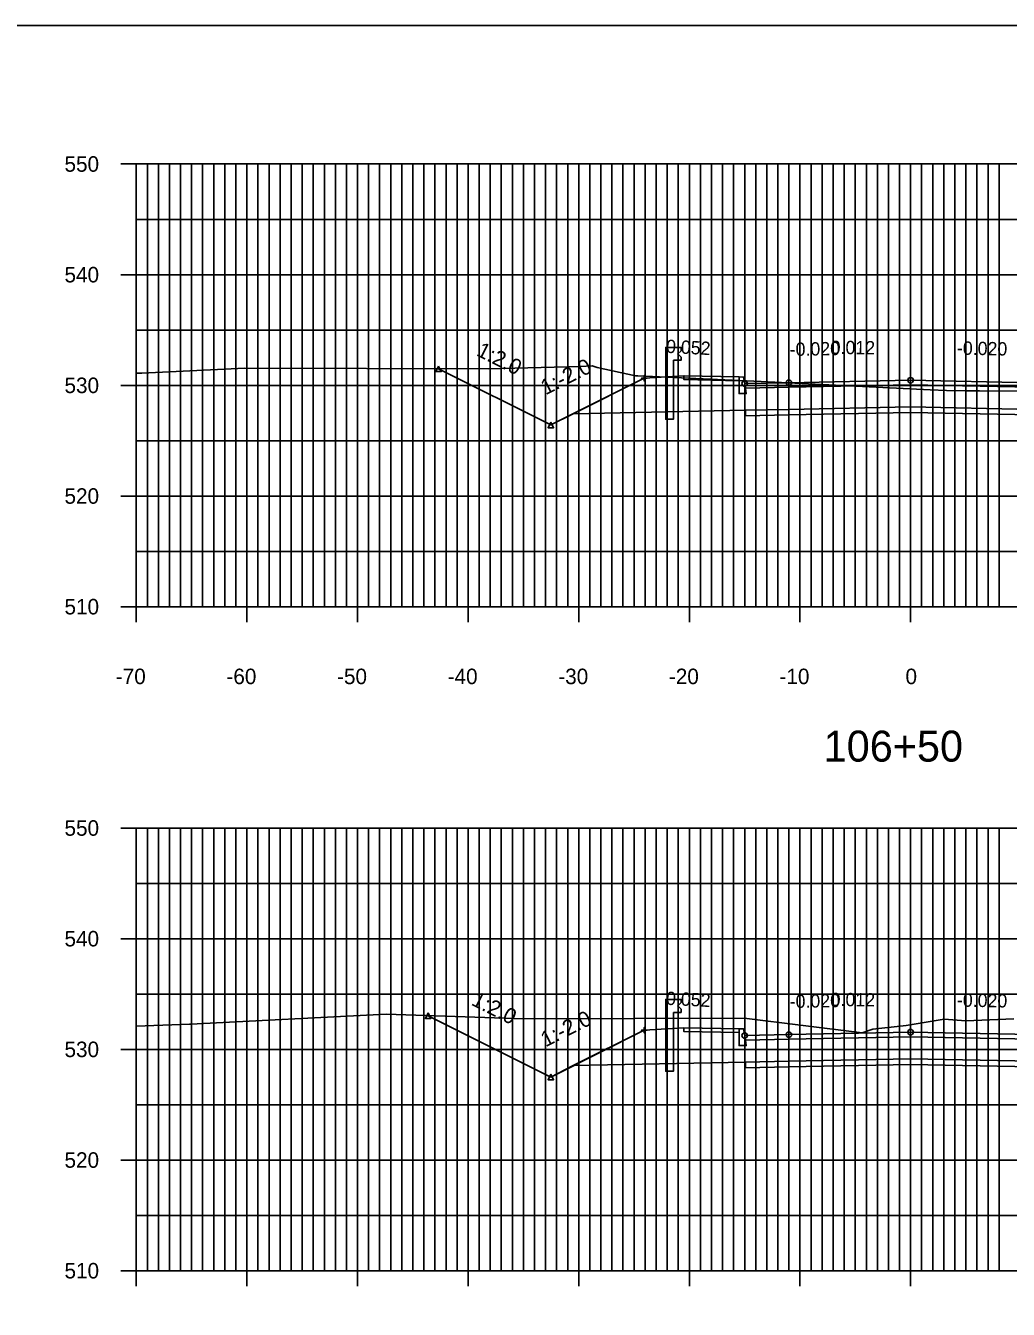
# Model space of a CAD drawing. Extents: x 1509063 to 1512863, y 401160 to 402918.
# Drawn here: x 1511982.7 to 1512071.6, y 402346.1 to 402462.1 of the extents above; entities that cross this region are included whole.
import ezdxf

# ---------------------------------------------------------------- set-up
doc = ezdxf.new("R2010")
doc.units = 0
for name, color, linetype in [('DD_P', 7, 'Continuous'), ('LCUT_P', 7, 'Continuous'), ('NBL1', 7, 'Continuous'), ('PET_P', 7, 'Continuous'), ('PRC', 7, 'Continuous'), ('PSP_P', 7, 'Continuous'), ('RBS_P', 7, 'Continuous'), ('RCC_P', 7, 'Continuous'), ('RGR_P', 7, 'Continuous'), ('XAX_P', 7, 'Continuous'), ('XAXTIC_P', 7, 'Continuous'), ('XAXTXT_P_T', 7, 'Continuous'), ('XGL_P', 7, 'Continuous'), ('XSL1_P', 7, 'Continuous'), ('XSL1_P_T', 7, 'Continuous'), ('XSL2_P', 7, 'Continuous'), ('XSL3_P', 7, 'Continuous'), ('XSLOG', 7, 'Continuous')]:
    doc.layers.add(name, color=color, linetype=linetype)

msp = doc.modelspace()

# ---------------------------------------------------------------- linework, layer by layer
at = {"layer": 'DD_P'}
for points in [[(1512042.23, 402430.44), (1512038.65, 402430.22), (1512030.2, 402426), (1512020.05, 402431.07)], [(1512042.23, 402371.52), (1512038.65, 402371.31), (1512030.2, 402367.08), (1512019.12, 402372.62)]]:
    msp.add_lwpolyline(points, dxfattribs=at)
for points in [[(1512030.2, 402426.25), (1512030.45, 402425.75), (1512029.95, 402425.75)], [(1512030.2, 402367.33), (1512030.45, 402366.83), (1512029.95, 402366.83)]]:
    msp.add_lwpolyline(points, close=True, dxfattribs=at)
at = {"layer": 'LCUT_P'}
for points in [[(1512020.05, 402431.32), (1512020.3, 402430.82), (1512019.8, 402430.82)], [(1512019.12, 402372.87), (1512019.37, 402372.37), (1512018.87, 402372.37)]]:
    msp.add_lwpolyline(points, close=True, dxfattribs=at)
at = {"layer": 'NBL1'}
msp.add_lwpolyline([(1512142.73, 402252.08), (1511822.73, 402252.08), (1511822.73, 402462.08), (1512142.73, 402462.08)], close=True, dxfattribs=at)
at = {"layer": 'PET_P'}
for centre in [(1512051.73, 402429.82), (1512051.73, 402370.91)]:
    msp.add_circle(centre, 0.25, dxfattribs=at)
at = {"layer": 'PRC'}
for centre in [(1512062.73, 402430.04), (1512062.73, 402371.13)]:
    msp.add_circle(centre, 0.25, dxfattribs=at)
at = {"layer": 'PSP_P'}
for centre in [(1512047.73, 402429.74), (1512047.73, 402370.83)]:
    msp.add_circle(centre, 0.25, dxfattribs=at)
at = {"layer": 'RBS_P'}
for points in [[(1512038.65, 402430.22), (1512038.65, 402430.47), (1512038.65, 402430.22), (1512038.4, 402430.22), (1512038.65, 402430.22), (1512038.65, 402429.97), (1512038.65, 402430.22), (1512038.9, 402430.22)], [(1512038.65, 402371.31), (1512038.65, 402371.56), (1512038.65, 402371.31), (1512038.4, 402371.31), (1512038.65, 402371.31), (1512038.65, 402371.06), (1512038.65, 402371.31), (1512038.9, 402371.31)]]:
    msp.add_lwpolyline(points, dxfattribs=at)
for points in [[(1512047.8, 402429.33), (1512051.73, 402429.41), (1512062.72, 402429.63), (1512062.72, 402427.63), (1512051.73, 402427.41), (1512047.8, 402427.33), (1512032.24, 402427.02), (1512038.65, 402430.22), (1512042.23, 402430.44), (1512042.23, 402430.1), (1512047.23, 402430), (1512047.23, 402428.84), (1512047.88, 402428.84)], [(1512062.72, 402429.63), (1512062.72, 402427.63), (1512073.73, 402427.41), (1512077.73, 402427.33), (1512088.24, 402427.12), (1512077.73, 402429.74), (1512077.73, 402429.33), (1512073.73, 402429.41)], [(1512047.8, 402370.42), (1512051.73, 402370.5), (1512062.72, 402370.72), (1512062.72, 402368.72), (1512051.73, 402368.5), (1512047.8, 402368.42), (1512032.24, 402368.11), (1512038.65, 402371.31), (1512042.23, 402371.52), (1512042.23, 402371.19), (1512047.23, 402371.09), (1512047.23, 402369.92), (1512047.88, 402369.92)], [(1512062.72, 402370.72), (1512062.72, 402368.72), (1512073.73, 402368.5), (1512077.73, 402368.42), (1512088.24, 402368.21), (1512077.73, 402370.83), (1512077.73, 402370.42), (1512073.73, 402370.5)]]:
    msp.add_lwpolyline(points, close=True, dxfattribs=at)
at = {"layer": 'RCC_P'}
for points in [[(1512047.73, 402429.74), (1512047.63, 402430.33), (1512047.23, 402430.34), (1512047.23, 402428.84), (1512047.88, 402428.84)], [(1512047.73, 402370.83), (1512047.63, 402371.42), (1512047.23, 402371.42), (1512047.23, 402369.92), (1512047.88, 402369.92)]]:
    msp.add_lwpolyline(points, close=True, dxfattribs=at)
at = {"layer": 'RGR_P'}
for points in [[(1512041.29, 402431.84), (1512041.98, 402431.84), (1512041.98, 402432.14), (1512041.68, 402432.42), (1512041.98, 402432.71), (1512041.98, 402433.01), (1512040.6, 402433.01), (1512040.6, 402426.51), (1512041.29, 402426.51)], [(1512041.29, 402372.92), (1512041.98, 402372.92), (1512041.98, 402373.22), (1512041.68, 402373.51), (1512041.98, 402373.8), (1512041.98, 402374.1), (1512040.6, 402374.1), (1512040.6, 402367.6), (1512041.29, 402367.6)]]:
    msp.add_lwpolyline(points, close=True, dxfattribs=at)
at = {"layer": 'XAX_P'}
for p, q in [((1511992.73, 402409.58), (1511992.73, 402449.58)), ((1512062.73, 402409.58), (1512062.73, 402449.58)), ((1511992.73, 402409.58), (1512132.73, 402409.58)), ((1511992.73, 402349.58), (1511992.73, 402389.58)), ((1512062.73, 402349.58), (1512062.73, 402389.58)), ((1511992.73, 402349.58), (1512132.73, 402349.58))]:
    msp.add_line(p, q, dxfattribs=at)
at = {"layer": 'XAXTIC_P'}
for p, q in [((1511991.33, 402449.58), (1511994.13, 402449.58)), ((1512061.33, 402449.58), (1512064.13, 402449.58)), ((1511991.33, 402439.58), (1511994.13, 402439.58)), ((1512061.33, 402439.58), (1512064.13, 402439.58)), ((1511991.33, 402429.58), (1511994.13, 402429.58)), ((1512061.33, 402429.58), (1512064.13, 402429.58)), ((1511991.33, 402419.58), (1511994.13, 402419.58)), ((1512061.33, 402419.58), (1512064.13, 402419.58)), ((1511992.73, 402408.18), (1511992.73, 402410.98)), ((1512002.73, 402408.18), (1512002.73, 402410.98)), ((1512012.73, 402408.18), (1512012.73, 402410.98)), ((1512022.73, 402408.18), (1512022.73, 402410.98)), ((1512032.73, 402408.18), (1512032.73, 402410.98)), ((1512042.73, 402408.18), (1512042.73, 402410.98)), ((1512052.73, 402408.18), (1512052.73, 402410.98)), ((1512062.73, 402408.18), (1512062.73, 402410.98)), ((1511991.33, 402409.58), (1511994.13, 402409.58)), ((1512061.33, 402409.58), (1512064.13, 402409.58)), ((1511991.33, 402389.58), (1511994.13, 402389.58)), ((1512061.33, 402389.58), (1512064.13, 402389.58)), ((1511991.33, 402379.58), (1511994.13, 402379.58)), ((1512061.33, 402379.58), (1512064.13, 402379.58)), ((1511991.33, 402369.58), (1511994.13, 402369.58)), ((1512061.33, 402369.58), (1512064.13, 402369.58)), ((1511991.33, 402359.58), (1511994.13, 402359.58)), ((1512061.33, 402359.58), (1512064.13, 402359.58)), ((1511992.73, 402348.18), (1511992.73, 402350.98)), ((1512002.73, 402348.18), (1512002.73, 402350.98)), ((1512012.73, 402348.18), (1512012.73, 402350.98)), ((1512022.73, 402348.18), (1512022.73, 402350.98)), ((1512032.73, 402348.18), (1512032.73, 402350.98)), ((1512042.73, 402348.18), (1512042.73, 402350.98)), ((1512052.73, 402348.18), (1512052.73, 402350.98)), ((1512062.73, 402348.18), (1512062.73, 402350.98)), ((1511991.33, 402349.58), (1511994.13, 402349.58)), ((1512061.33, 402349.58), (1512064.13, 402349.58))]:
    msp.add_line(p, q, dxfattribs=at)
at = {"layer": 'XGL_P'}
for p, q in [((1511992.73, 402449.58), (1512132.73, 402449.58)), ((1511992.73, 402409.58), (1511992.73, 402449.58)), ((1511993.73, 402409.58), (1511993.73, 402449.58)), ((1511994.73, 402409.58), (1511994.73, 402449.58)), ((1511995.73, 402409.58), (1511995.73, 402449.58)), ((1511996.73, 402409.58), (1511996.73, 402449.58)), ((1511997.73, 402409.58), (1511997.73, 402449.58)), ((1511998.73, 402409.58), (1511998.73, 402449.58)), ((1511999.73, 402409.58), (1511999.73, 402449.58)), ((1512000.73, 402409.58), (1512000.73, 402449.58)), ((1512001.73, 402409.58), (1512001.73, 402449.58)), ((1512002.73, 402409.58), (1512002.73, 402449.58)), ((1512003.73, 402409.58), (1512003.73, 402449.58)), ((1512004.73, 402409.58), (1512004.73, 402449.58)), ((1512005.73, 402409.58), (1512005.73, 402449.58)), ((1512006.73, 402409.58), (1512006.73, 402449.58)), ((1512007.73, 402409.58), (1512007.73, 402449.58)), ((1512008.73, 402409.58), (1512008.73, 402449.58)), ((1512009.73, 402409.58), (1512009.73, 402449.58)), ((1512010.73, 402409.58), (1512010.73, 402449.58)), ((1512011.73, 402409.58), (1512011.73, 402449.58)), ((1512012.73, 402409.58), (1512012.73, 402449.58)), ((1512013.73, 402409.58), (1512013.73, 402449.58)), ((1512014.73, 402409.58), (1512014.73, 402449.58)), ((1512015.73, 402409.58), (1512015.73, 402449.58)), ((1512016.73, 402409.58), (1512016.73, 402449.58)), ((1512017.73, 402409.58), (1512017.73, 402449.58)), ((1512018.73, 402409.58), (1512018.73, 402449.58)), ((1512019.73, 402409.58), (1512019.73, 402449.58)), ((1512020.73, 402409.58), (1512020.73, 402449.58)), ((1512021.73, 402409.58), (1512021.73, 402449.58)), ((1512022.73, 402409.58), (1512022.73, 402449.58)), ((1512023.73, 402409.58), (1512023.73, 402449.58)), ((1512024.73, 402409.58), (1512024.73, 402449.58)), ((1512025.73, 402409.58), (1512025.73, 402449.58)), ((1512026.73, 402409.58), (1512026.73, 402449.58)), ((1512027.73, 402409.58), (1512027.73, 402449.58)), ((1512028.73, 402409.58), (1512028.73, 402449.58)), ((1512029.73, 402409.58), (1512029.73, 402449.58)), ((1512030.73, 402409.58), (1512030.73, 402449.58)), ((1512031.73, 402409.58), (1512031.73, 402449.58)), ((1512032.73, 402409.58), (1512032.73, 402449.58)), ((1512033.73, 402409.58), (1512033.73, 402449.58)), ((1512034.73, 402409.58), (1512034.73, 402449.58)), ((1512035.73, 402409.58), (1512035.73, 402449.58)), ((1512036.73, 402409.58), (1512036.73, 402449.58)), ((1512037.73, 402409.58), (1512037.73, 402449.58)), ((1512038.73, 402409.58), (1512038.73, 402449.58)), ((1512039.73, 402409.58), (1512039.73, 402449.58)), ((1512040.73, 402409.58), (1512040.73, 402449.58)), ((1512041.73, 402409.58), (1512041.73, 402449.58)), ((1512042.73, 402409.58), (1512042.73, 402449.58)), ((1512043.73, 402409.58), (1512043.73, 402449.58)), ((1512044.73, 402409.58), (1512044.73, 402449.58)), ((1512045.73, 402409.58), (1512045.73, 402449.58)), ((1512046.73, 402409.58), (1512046.73, 402449.58)), ((1512047.73, 402409.58), (1512047.73, 402449.58)), ((1512048.73, 402409.58), (1512048.73, 402449.58)), ((1512049.73, 402409.58), (1512049.73, 402449.58)), ((1512050.73, 402409.58), (1512050.73, 402449.58)), ((1512051.73, 402409.58), (1512051.73, 402449.58)), ((1512052.73, 402409.58), (1512052.73, 402449.58)), ((1512053.73, 402409.58), (1512053.73, 402449.58)), ((1512054.73, 402409.58), (1512054.73, 402449.58)), ((1512055.73, 402409.58), (1512055.73, 402449.58)), ((1512056.73, 402409.58), (1512056.73, 402449.58)), ((1512057.73, 402409.58), (1512057.73, 402449.58)), ((1512058.73, 402409.58), (1512058.73, 402449.58)), ((1512059.73, 402409.58), (1512059.73, 402449.58)), ((1512060.73, 402409.58), (1512060.73, 402449.58)), ((1512061.73, 402409.58), (1512061.73, 402449.58)), ((1512062.73, 402409.58), (1512062.73, 402449.58)), ((1512063.73, 402409.58), (1512063.73, 402449.58)), ((1512064.73, 402409.58), (1512064.73, 402449.58)), ((1512065.73, 402409.58), (1512065.73, 402449.58)), ((1512066.73, 402409.58), (1512066.73, 402449.58)), ((1512067.73, 402409.58), (1512067.73, 402449.58)), ((1512068.73, 402409.58), (1512068.73, 402449.58)), ((1512069.73, 402409.58), (1512069.73, 402449.58)), ((1512070.73, 402409.58), (1512070.73, 402449.58)), ((1511992.73, 402444.58), (1512132.73, 402444.58)), ((1511992.73, 402439.58), (1512132.73, 402439.58)), ((1511992.73, 402434.58), (1512132.73, 402434.58)), ((1511992.73, 402429.58), (1512132.73, 402429.58)), ((1511992.73, 402424.58), (1512132.73, 402424.58)), ((1511992.73, 402419.58), (1512132.73, 402419.58)), ((1511992.73, 402414.58), (1512132.73, 402414.58)), ((1511992.73, 402409.58), (1512132.73, 402409.58)), ((1511992.73, 402389.58), (1512132.73, 402389.58)), ((1511992.73, 402349.58), (1511992.73, 402389.58)), ((1511993.73, 402349.58), (1511993.73, 402389.58)), ((1511994.73, 402349.58), (1511994.73, 402389.58)), ((1511995.73, 402349.58), (1511995.73, 402389.58)), ((1511996.73, 402349.58), (1511996.73, 402389.58)), ((1511997.73, 402349.58), (1511997.73, 402389.58)), ((1511998.73, 402349.58), (1511998.73, 402389.58)), ((1511999.73, 402349.58), (1511999.73, 402389.58)), ((1512000.73, 402349.58), (1512000.73, 402389.58)), ((1512001.73, 402349.58), (1512001.73, 402389.58)), ((1512002.73, 402349.58), (1512002.73, 402389.58)), ((1512003.73, 402349.58), (1512003.73, 402389.58)), ((1512004.73, 402349.58), (1512004.73, 402389.58)), ((1512005.73, 402349.58), (1512005.73, 402389.58)), ((1512006.73, 402349.58), (1512006.73, 402389.58)), ((1512007.73, 402349.58), (1512007.73, 402389.58)), ((1512008.73, 402349.58), (1512008.73, 402389.58)), ((1512009.73, 402349.58), (1512009.73, 402389.58)), ((1512010.73, 402349.58), (1512010.73, 402389.58)), ((1512011.73, 402349.58), (1512011.73, 402389.58)), ((1512012.73, 402349.58), (1512012.73, 402389.58)), ((1512013.73, 402349.58), (1512013.73, 402389.58)), ((1512014.73, 402349.58), (1512014.73, 402389.58)), ((1512015.73, 402349.58), (1512015.73, 402389.58)), ((1512016.73, 402349.58), (1512016.73, 402389.58)), ((1512017.73, 402349.58), (1512017.73, 402389.58)), ((1512018.73, 402349.58), (1512018.73, 402389.58)), ((1512019.73, 402349.58), (1512019.73, 402389.58)), ((1512020.73, 402349.58), (1512020.73, 402389.58)), ((1512021.73, 402349.58), (1512021.73, 402389.58)), ((1512022.73, 402349.58), (1512022.73, 402389.58)), ((1512023.73, 402349.58), (1512023.73, 402389.58)), ((1512024.73, 402349.58), (1512024.73, 402389.58)), ((1512025.73, 402349.58), (1512025.73, 402389.58)), ((1512026.73, 402349.58), (1512026.73, 402389.58)), ((1512027.73, 402349.58), (1512027.73, 402389.58)), ((1512028.73, 402349.58), (1512028.73, 402389.58)), ((1512029.73, 402349.58), (1512029.73, 402389.58)), ((1512030.73, 402349.58), (1512030.73, 402389.58)), ((1512031.73, 402349.58), (1512031.73, 402389.58)), ((1512032.73, 402349.58), (1512032.73, 402389.58)), ((1512033.73, 402349.58), (1512033.73, 402389.58)), ((1512034.73, 402349.58), (1512034.73, 402389.58)), ((1512035.73, 402349.58), (1512035.73, 402389.58)), ((1512036.73, 402349.58), (1512036.73, 402389.58)), ((1512037.73, 402349.58), (1512037.73, 402389.58)), ((1512038.73, 402349.58), (1512038.73, 402389.58)), ((1512039.73, 402349.58), (1512039.73, 402389.58)), ((1512040.73, 402349.58), (1512040.73, 402389.58)), ((1512041.73, 402349.58), (1512041.73, 402389.58)), ((1512042.73, 402349.58), (1512042.73, 402389.58)), ((1512043.73, 402349.58), (1512043.73, 402389.58)), ((1512044.73, 402349.58), (1512044.73, 402389.58)), ((1512045.73, 402349.58), (1512045.73, 402389.58)), ((1512046.73, 402349.58), (1512046.73, 402389.58)), ((1512047.73, 402349.58), (1512047.73, 402389.58)), ((1512048.73, 402349.58), (1512048.73, 402389.58)), ((1512049.73, 402349.58), (1512049.73, 402389.58)), ((1512050.73, 402349.58), (1512050.73, 402389.58)), ((1512051.73, 402349.58), (1512051.73, 402389.58)), ((1512052.73, 402349.58), (1512052.73, 402389.58)), ((1512053.73, 402349.58), (1512053.73, 402389.58)), ((1512054.73, 402349.58), (1512054.73, 402389.58)), ((1512055.73, 402349.58), (1512055.73, 402389.58)), ((1512056.73, 402349.58), (1512056.73, 402389.58)), ((1512057.73, 402349.58), (1512057.73, 402389.58)), ((1512058.73, 402349.58), (1512058.73, 402389.58)), ((1512059.73, 402349.58), (1512059.73, 402389.58)), ((1512060.73, 402349.58), (1512060.73, 402389.58)), ((1512061.73, 402349.58), (1512061.73, 402389.58)), ((1512062.73, 402349.58), (1512062.73, 402389.58)), ((1512063.73, 402349.58), (1512063.73, 402389.58)), ((1512064.73, 402349.58), (1512064.73, 402389.58)), ((1512065.73, 402349.58), (1512065.73, 402389.58)), ((1512066.73, 402349.58), (1512066.73, 402389.58)), ((1512067.73, 402349.58), (1512067.73, 402389.58)), ((1512068.73, 402349.58), (1512068.73, 402389.58)), ((1512069.73, 402349.58), (1512069.73, 402389.58)), ((1512070.73, 402349.58), (1512070.73, 402389.58)), ((1511992.73, 402384.58), (1512132.73, 402384.58)), ((1511992.73, 402379.58), (1512132.73, 402379.58)), ((1511992.73, 402374.58), (1512132.73, 402374.58)), ((1511992.73, 402369.58), (1512132.73, 402369.58)), ((1511992.73, 402364.58), (1512132.73, 402364.58)), ((1511992.73, 402359.58), (1512132.73, 402359.58)), ((1511992.73, 402354.58), (1512132.73, 402354.58)), ((1511992.73, 402349.58), (1512132.73, 402349.58))]:
    msp.add_line(p, q, dxfattribs=at)
at = {"layer": 'XSL1_P'}
for points in [[(1512020.05, 402431.07), (1512030.2, 402426), (1512032.24, 402427.02), (1512038.65, 402430.22), (1512042.23, 402430.44), (1512047.23, 402430.34), (1512047.63, 402430.33), (1512047.73, 402429.74), (1512051.73, 402429.82), (1512062.73, 402430.04), (1512073.73, 402429.82), (1512077.73, 402429.74), (1512088.24, 402427.12), (1512090.41, 402426.57), (1512097.79, 402424.73), (1512104.83, 402428.24)], [(1512019.12, 402372.62), (1512030.2, 402367.08), (1512032.24, 402368.11), (1512038.65, 402371.31), (1512042.23, 402371.52), (1512047.23, 402371.42), (1512047.63, 402371.42), (1512047.73, 402370.83), (1512051.73, 402370.91), (1512062.73, 402371.13), (1512073.73, 402370.91), (1512077.73, 402370.83), (1512088.24, 402368.21), (1512090.41, 402367.66), (1512100.15, 402365.23)]]:
    msp.add_lwpolyline(points, dxfattribs=at)
for points in [[(1512047.23, 402430.34), (1512042.23, 402430.44), (1512042.23, 402430.1), (1512047.23, 402430)], [(1512047.23, 402371.42), (1512042.23, 402371.52), (1512042.23, 402371.19), (1512047.23, 402371.09)]]:
    msp.add_lwpolyline(points, close=True, dxfattribs=at)
at = {"layer": 'XSL2_P'}
for points in [[(1512047.8, 402427.33), (1512032.24, 402427.02)], [(1512032.24, 402368.11), (1512047.8, 402368.42)]]:
    msp.add_lwpolyline(points, dxfattribs=at)
for points in [[(1512073.73, 402426.91), (1512062.72, 402427.13), (1512051.73, 402426.91), (1512047.8, 402426.83), (1512047.8, 402427.33), (1512051.73, 402427.41), (1512062.72, 402427.63), (1512073.73, 402427.41), (1512077.73, 402427.33), (1512077.73, 402426.83)], [(1512073.73, 402368), (1512062.72, 402368.22), (1512051.73, 402368), (1512047.8, 402367.92), (1512047.8, 402368.42), (1512051.73, 402368.5), (1512062.72, 402368.72), (1512073.73, 402368.5), (1512077.73, 402368.42), (1512077.73, 402367.92)]]:
    msp.add_lwpolyline(points, close=True, dxfattribs=at)
at = {"layer": 'XSL3_P'}
for points in [[(1512051.73, 402429.41), (1512047.8, 402429.33), (1512047.73, 402429.74), (1512051.73, 402429.82), (1512062.72, 402430.04), (1512073.73, 402429.82), (1512077.73, 402429.74), (1512077.73, 402429.33), (1512073.73, 402429.41), (1512062.72, 402429.63)], [(1512051.73, 402370.5), (1512047.8, 402370.42), (1512047.73, 402370.83), (1512051.73, 402370.91), (1512062.72, 402371.13), (1512073.73, 402370.91), (1512077.73, 402370.83), (1512077.73, 402370.42), (1512073.73, 402370.5), (1512062.72, 402370.72)]]:
    msp.add_lwpolyline(points, close=True, dxfattribs=at)
at = {"layer": 'XSLOG'}
for points in [[(1511992.73, 402430.68), (1511993.22, 402430.68), (1512002.54, 402431.12), (1512024.56, 402431.06), (1512032.9, 402431.29), (1512033.95, 402431.33), (1512034.4, 402431.19), (1512037.87, 402430.44), (1512038.07, 402430.43), (1512049.21, 402429.93), (1512064.5, 402429.18), (1512065.97, 402429.11), (1512067.69, 402429.08), (1512068.97, 402429.07), (1512076.34, 402429.03)], [(1511992.73, 402371.69), (1511997.55, 402371.87), (1511997.58, 402371.87), (1511997.63, 402371.87), (1512015.32, 402372.75), (1512027.8, 402372.33), (1512047.68, 402372.4), (1512058.36, 402371.08), (1512059.32, 402371.39), (1512062.33, 402371.75), (1512065.76, 402372.32), (1512067.73, 402372.17), (1512072.06, 402372.35)]]:
    msp.add_lwpolyline(points, dxfattribs=at)

# ---------------------------------------------------------------- texts
at = {"layer": 'XAXTXT_P_T'}
for s, height, p in [('550', 1.4, (1511986.24, 402448.88)), ('540', 1.4, (1511986.24, 402438.88)), ('530', 1.4, (1511986.24, 402428.88)), ('520', 1.4, (1511986.24, 402418.88)), ('510', 1.4, (1511986.24, 402408.88)), ('-70', 1.4, (1511990.88, 402402.58)), ('-60', 1.4, (1512000.88, 402402.58)), ('-50', 1.4, (1512010.88, 402402.58)), ('-40', 1.4, (1512020.88, 402402.58)), ('-30', 1.4, (1512030.88, 402402.58)), ('-20', 1.4, (1512040.88, 402402.58)), ('-10', 1.4, (1512050.88, 402402.58)), ('0', 1.4, (1512062.27, 402402.58)), ('106+50', 2.8, (1512054.87, 402395.58)), ('550', 1.4, (1511986.24, 402388.88)), ('540', 1.4, (1511986.24, 402378.88)), ('530', 1.4, (1511986.24, 402368.88)), ('520', 1.4, (1511986.24, 402358.88)), ('510', 1.4, (1511986.24, 402348.88))]:
    msp.add_text(s, height=height, dxfattribs=at).set_placement(p)
at = {"layer": 'XSL1_P_T'}
for s, height, rotation, p in [('1:2.0', 1.4, 333.4349, (1512023.39, 402432.31)), ('1:2.0', 1.4, 333.4349, (1512023.39, 402432.31)), ('1:2.0', 1.4, 333.4349, (1512023.39, 402432.31)), ('0.052', 1.2, 356.9978, (1512040.6, 402432.52)), ('-0.020', 1.2, 1.1458, (1512051.81, 402432.23)), ('0.012', 1.2, 359.3017, (1512055.5, 402432.42)), ('0.012', 1.2, 359.3017, (1512055.5, 402432.42)), ('-0.020', 1.2, 358.8542, (1512066.91, 402432.36)), ('1:-2.0', 1.4, 26.5651, (1512029.74, 402428.68)), ('1:-2.0', 1.4, 26.5651, (1512029.74, 402428.68)), ('1:-2.0', 1.4, 26.5651, (1512029.74, 402428.68)), ('0.052', 1.2, 356.9978, (1512040.6, 402373.61)), ('1:2.0', 1.4, 333.4349, (1512022.93, 402373.63)), ('1:2.0', 1.4, 333.4349, (1512022.93, 402373.63)), ('1:2.0', 1.4, 333.4349, (1512022.93, 402373.63)), ('-0.020', 1.2, 1.1458, (1512051.81, 402373.31)), ('0.012', 1.2, 359.3017, (1512055.5, 402373.5)), ('0.012', 1.2, 359.3017, (1512055.5, 402373.5)), ('-0.020', 1.2, 358.8542, (1512066.91, 402373.45)), ('1:-2.0', 1.4, 26.5651, (1512029.74, 402369.76)), ('1:-2.0', 1.4, 26.5651, (1512029.74, 402369.76)), ('1:-2.0', 1.4, 26.5651, (1512029.74, 402369.76))]:
    msp.add_text(s, height=height, rotation=rotation, dxfattribs=at).set_placement(p)

doc.saveas('drawing.dxf')
